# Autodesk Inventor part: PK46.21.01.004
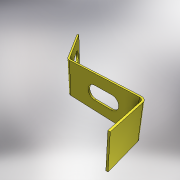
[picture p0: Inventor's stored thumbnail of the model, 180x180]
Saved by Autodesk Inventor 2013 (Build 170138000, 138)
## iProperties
Created: 2005-04
Part Number: PK46.21.01.004
Material: Steel, Mild
Document SubType Name: Sheet Metal
Designer: salex
Manufacturer: Standard
Standards Organization: Custom
Density: 7.86 g/cm^3
Sheet Metal Rule: Default
Author: salex
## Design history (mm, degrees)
node "ФлнОтгиб1"
sketch "Sketch2"
  geometry: L1 (161.943, 60)-(261.943, 60); L2 (261.943, 140)-(161.943, 140); L3 (0, 200)-(0, 0) reference; L4 (0, 0)-(396.943, 0) reference; L5 (396.943, 0)-(396.943, 200) reference; A1 r 40 centre (161.943, 100) between (161.943, 140) and (161.943, 60); A2 r 40 centre (261.943, 100) between (261.943, 60) and (261.943, 140); 1 further point
  constraints: 4 end point, 4 point on circle, 4 tangent, 2 centre point, 1 horizontal, 1 parallel
  dimensions: "d16" = 100 distance of A2.centre A1.centre; "d17" = 40 radius of A1; "d19" = 200 distance of L3.start L3.end (derived); "d20" = 100 distance from line of A1.centre L4 (= 0.5 x d19); "d23" = 135 distance from line of A2.centre L5
cut "Cut1" sketch "Sketch2" dims "d21" = 10 (= Thickness), "d22" = 0
sketch "Sketch3"
  geometry: L1 (60, -78.841)-(60, -138.841); L2 (140, -138.841)-(140, -78.841); L3 (0, 0)-(200, 0) reference; L4 (200, -256.224)-(200, 0) reference; A1 r 40 centre (100, -78.841) between (140, -78.841) and (60, -78.841); A2 r 40 centre (100, -138.841) between (60, -138.841) and (140, -138.841); 1 further point
  constraints: 4 end point, 4 point on circle, 4 tangent, 2 centre point, 1 parallel
  dimensions: "d24" = 60 distance of A2.centre A1.centre; "d25" = 40 radius of A1; "d26" = 78.84052 distance from line of A1.centre L3; "d27" = 100 distance from line of A1.centre L4 (= d20)
cut "Cut2" sketch "Sketch3" dims "d28" = 10 (= Thickness), "d29" = 0
body "Solid1"
sketch "Эскиз1"
  geometry: L1 (-165, 215)-(0, 0); L2 (0, 0)-(430, 0); L3 (430, 0)-(450, -220)
  constraints: 6 end point, 1 horizontal, 1 other
  dimensions: "d4" = 430 distance of L1.end L2.end; "d12" = 165 horizontal distance of L1.start L1.end; "d13" = 215 vertical distance of L1.start L1.end; "d14" = 220 vertical distance of L2.end L3.end; "d15" = 615 horizontal distance of L3.end L1.start
feature "Плакирование1" dims "d5" = 200, "d6" = 10 (= BendReliefWidth), "d8" = 20 (= MinimumRemnant), "d10" = 20 (= BendRadius), "d11" = 10, "Thickness" = 10
feature "Изгиб1" dims "d6" = 10 (= BendReliefWidth), "d7" = 5 (= BendReliefDepth), "d8" = 20 (= MinimumRemnant), "d9" = 20 (= BendRadius), "d10" = 20 (= BendRadius), "d11" = 10, "SeamGap" = 0.01, "Thickness" = 10
other parameters: "BendRadius" = 20, "BendReliefDepth" = 5 (= 0.5 x Thickness)
